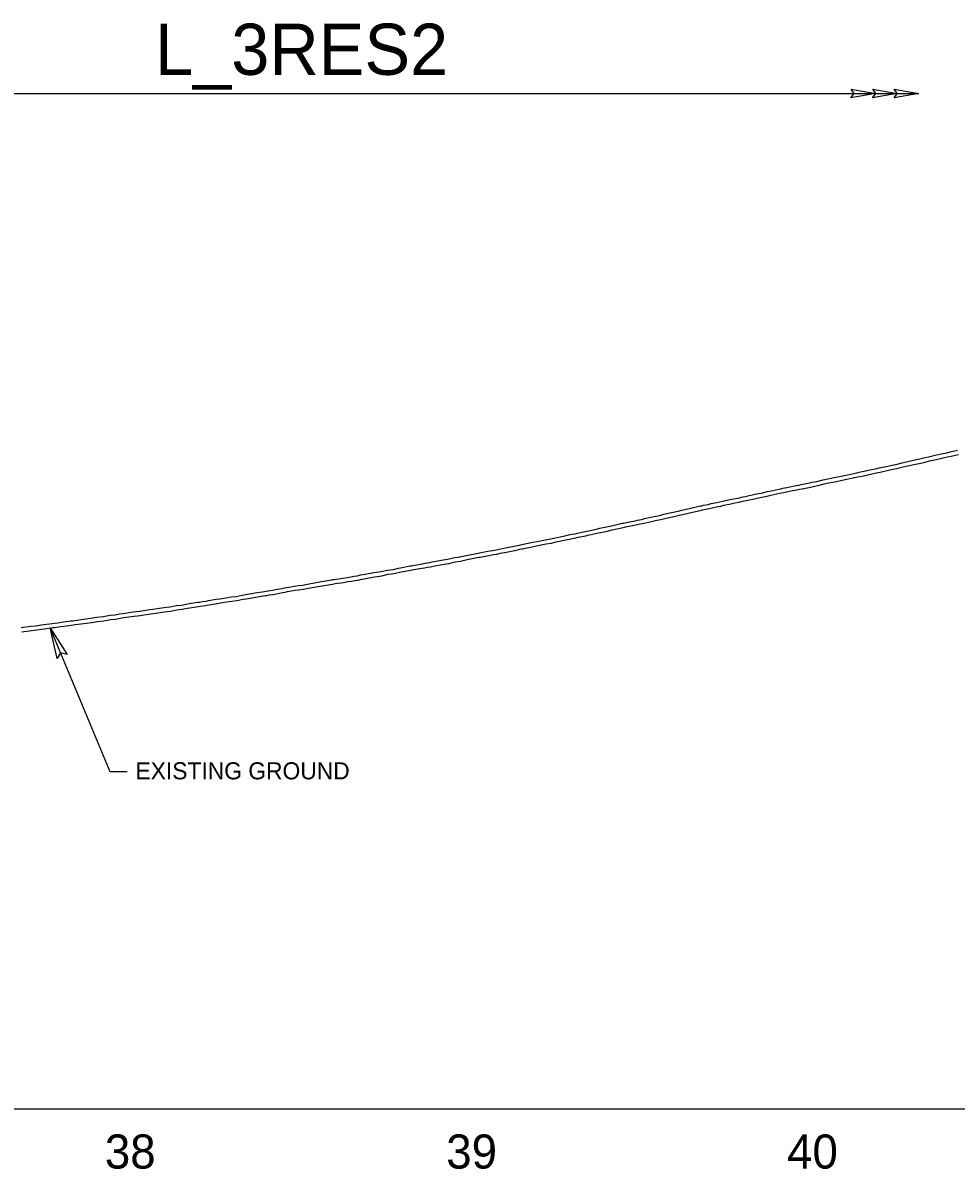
# Model space of a CAD drawing. Extents: x 2115752 to 2121174, y 562881 to 567245.
# Drawn here: x 2119464.8 to 2119738.2, y 566358.2 to 566694.2 of the extents above; entities that cross this region are included whole.
import ezdxf

# ---------------------------------------------------------------- set-up
doc = ezdxf.new("R2010")
doc.units = 0
for name, color, linetype in [('Exist Profile Cell', 7, 'Continuous'), ('Exist Vertical Profile Ground Line', 7, 'Continuous'), ('Exist Vertical Profile Horizontal Axis Label Major', 7, 'Continuous'), ('Prop Terminator CELL', 7, 'Continuous'), ('Prop VPI Label', 7, 'Continuous'), ('Scratch_Level_1', 7, 'Continuous')]:
    doc.layers.add(name, color=color, linetype=linetype)

msp = doc.modelspace()

# ---------------------------------------------------------------- linework, layer by layer
at = {"layer": 'Exist Profile Cell'}
msp.add_line((2116696.3, 566375.81), (2121174.42, 566375.81), dxfattribs=at)
at = {"layer": 'Exist Vertical Profile Ground Line'}
for points in [[(2119593.02, 566536.41), (2119594.92, 566536.88), (2119598.4, 566537.53), (2119598.78, 566537.61), (2119601.27, 566538.08), (2119602.62, 566538.34), (2119603.67, 566538.49), (2119604.59, 566538.7), (2119606.42, 566539.07), (2119607.87, 566539.37), (2119608.94, 566539.54), (2119610.39, 566539.9), (2119610.84, 566539.98), (2119611.18, 566540.05), (2119614.4, 566540.72), (2119615.66, 566540.98), (2119617.61, 566541.36), (2119617.98, 566541.44), (2119619.66, 566541.69), (2119621.01, 566542.03), (2119622.02, 566542.24), (2119624.23, 566542.72), (2119624.91, 566542.84), (2119625.83, 566543.06), (2119626.82, 566543.23), (2119627.5, 566543.39), (2119629.68, 566543.87), (2119630.29, 566543.98), (2119630.83, 566544.11), (2119633.41, 566544.67), (2119634.04, 566544.81), (2119635.59, 566545.09), (2119637.47, 566545.58), (2119640.62, 566546.26), (2119640.99, 566546.34), (2119641.38, 566546.43), (2119643.85, 566546.93), (2119644.4, 566547.04), (2119645.13, 566547.22), (2119646.25, 566547.43), (2119647.17, 566547.66), (2119648.99, 566548.06), (2119650.5, 566548.39), (2119651.67, 566548.61), (2119652.88, 566548.94), (2119653.75, 566549.14), (2119655.1, 566549.41), (2119657.04, 566549.88), (2119658.08, 566550.12), (2119660.62, 566550.7), (2119663.58, 566551.36), (2119663.93, 566551.44), (2119664.42, 566551.54), (2119665.82, 566551.79), (2119666.77, 566552.04), (2119668.34, 566552.39), (2119669.28, 566552.57), (2119670.15, 566552.78), (2119672.18, 566553.21), (2119673.36, 566553.46), (2119674.63, 566553.68), (2119676.14, 566554.05), (2119676.71, 566554.18), (2119679.49, 566554.79), (2119679.96, 566554.89), (2119681.81, 566555.24), (2119683.17, 566555.58), (2119683.87, 566555.74), (2119686.53, 566556.3), (2119687.07, 566556.41), (2119687.74, 566556.56), (2119688.89, 566556.78), (2119689.76, 566556.97), (2119691.57, 566557.33), (2119692.36, 566557.47), (2119693.1, 566557.63), (2119695.5, 566558.12), (2119696.31, 566558.29), (2119697.68, 566558.56), (2119699.56, 566559.03), (2119700.93, 566559.32), (2119703.17, 566559.8), (2119704.82, 566560.1), (2119706.17, 566560.42), (2119707.1, 566560.63), (2119709.38, 566561.11), (2119710.1, 566561.26), (2119710.98, 566561.46), (2119711.97, 566561.65), (2119712.73, 566561.81), (2119714.83, 566562.26), (2119715.95, 566562.53), (2119718.44, 566563.07), (2119718.85, 566563.15), (2119719.24, 566563.25), (2119720.79, 566563.54), (2119722.69, 566564.03), (2119726.33, 566564.86), (2119727.87, 566565.17), (2119729.01, 566565.46), (2119730.38, 566565.78)], [(2119730.38, 566565.78), (2119732.36, 566566.24), (2119734.06, 566566.61), (2119735.72, 566566.98), (2119736.75, 566567.2), (2119738.06, 566567.51), (2119738.89, 566567.69)], [(2119464.41, 566515.72), (2119467.25, 566516.09), (2119468.83, 566516.24), (2119470.32, 566516.48), (2119471.04, 566516.58), (2119473.53, 566516.91), (2119474.25, 566516.99), (2119475.12, 566517.12), (2119476.79, 566517.34), (2119478.92, 566517.64), (2119479.56, 566517.71), (2119480.11, 566517.81), (2119482.65, 566518.16), (2119483.34, 566518.26), (2119484.88, 566518.43), (2119486.64, 566518.73), (2119488.42, 566518.94), (2119489.98, 566519.21), (2119490.53, 566519.29), (2119491.92, 566519.44), (2119493.3, 566519.69), (2119494.31, 566519.84), (2119496.53, 566520.17), (2119497.26, 566520.27), (2119498.2, 566520.4), (2119499.07, 566520.48), (2119499.69, 566520.59), (2119502.12, 566520.94), (2119502.99, 566521.07), (2119506.29, 566521.57), (2119507.98, 566521.75), (2119509.89, 566522.13), (2119511.39, 566522.28), (2119512.86, 566522.58), (2119513.69, 566522.71), (2119516.1, 566523.1), (2119516.71, 566523.19), (2119517.56, 566523.34), (2119518.61, 566523.46), (2119519.37, 566523.61), (2119521.54, 566523.97), (2119522.65, 566524.14), (2119525.12, 566524.54), (2119525.96, 566524.66), (2119527.44, 566524.83), (2119529.29, 566525.23), (2119530.21, 566525.39), (2119532.53, 566525.77), (2119532.9, 566525.84), (2119535.76, 566526.3), (2119536.24, 566526.37), (2119536.88, 566526.5), (2119538.13, 566526.66), (2119539.05, 566526.86), (2119540.82, 566527.18), (2119541.61, 566527.3), (2119542.33, 566527.46), (2119544.54, 566527.85), (2119545.58, 566528.02), (2119546.88, 566528.14), (2119548.89, 566528.56), (2119552.46, 566529.19), (2119555.5, 566529.7), (2119555.83, 566529.75), (2119556.23, 566529.83), (2119558.74, 566530.19), (2119559.99, 566530.4), (2119561.05, 566530.56), (2119562.03, 566530.75), (2119562.97, 566530.87), (2119564.06, 566531.14), (2119564.71, 566531.25), (2119565.29, 566531.36), (2119567.77, 566531.81), (2119568.57, 566531.95), (2119569.94, 566532.12), (2119571.8, 566532.57), (2119573.54, 566532.77), (2119575.09, 566533.14), (2119575.61, 566533.23), (2119578.43, 566533.75), (2119578.85, 566533.82), (2119579.29, 566533.92), (2119581.62, 566534.33), (2119582.4, 566534.45), (2119583.35, 566534.65), (2119584.23, 566534.78), (2119584.93, 566534.94), (2119587.13, 566535.37), (2119587.67, 566535.45), (2119588.16, 566535.55), (2119589.56, 566535.75), (2119591.06, 566536.14), (2119591.51, 566536.23), (2119593.02, 566536.41)]]:
    msp.add_lwpolyline(points, dxfattribs=at)
at = {"layer": 'Prop Terminator CELL'}
msp.add_lwpolyline([(2119474.8, 566507.9), (2119472.77, 566516.81), (2119477.73, 566509.07), (2119475.81, 566509.51)], close=True, dxfattribs=at)
at = {"layer": 'Prop VPI Label'}
msp.add_lwpolyline([(2119495.3, 566474.67), (2119490.33, 566474.67), (2119472.77, 566516.81)], dxfattribs=at)
at = {"layer": 'Scratch_Level_1'}
msp.add_line((2119356.3, 566673.51), (2119727.28, 566673.51), dxfattribs=at)
for points in [[(2119707.44, 566674.75), (2119714.64, 566673.51), (2119707.4, 566672.23), (2119708.32, 566673.51)], [(2119713.76, 566674.75), (2119720.96, 566673.51), (2119713.72, 566672.23), (2119714.64, 566673.51)], [(2119720.08, 566674.75), (2119727.28, 566673.51), (2119720.04, 566672.23), (2119720.96, 566673.51)]]:
    msp.add_lwpolyline(points, close=True, dxfattribs=at)
for points in [[(2119730.1, 566567), (2119732.09, 566567.45), (2119733.79, 566567.83), (2119735.46, 566568.2), (2119736.47, 566568.42), (2119737.78, 566568.73), (2119738.62, 566568.91)], [(2119592.72, 566537.63), (2119594.65, 566538.1), (2119598.16, 566538.76), (2119598.54, 566538.84), (2119601.03, 566539.31), (2119602.41, 566539.57), (2119603.44, 566539.72), (2119604.32, 566539.93), (2119606.17, 566540.3), (2119607.65, 566540.6), (2119608.69, 566540.77), (2119610.13, 566541.12), (2119610.6, 566541.21), (2119610.92, 566541.27), (2119614.15, 566541.95), (2119615.42, 566542.21), (2119617.36, 566542.59), (2119617.76, 566542.67), (2119619.42, 566542.92), (2119620.73, 566543.25), (2119621.76, 566543.46), (2119623.99, 566543.94), (2119624.65, 566544.07), (2119625.58, 566544.28), (2119626.57, 566544.45), (2119627.22, 566544.61), (2119629.43, 566545.09), (2119630.03, 566545.21), (2119630.56, 566545.33), (2119633.14, 566545.89), (2119633.79, 566546.03), (2119635.32, 566546.32), (2119637.19, 566546.79), (2119640.36, 566547.49), (2119640.72, 566547.56), (2119641.11, 566547.65), (2119643.61, 566548.16), (2119644.13, 566548.26), (2119644.86, 566548.44), (2119645.98, 566548.66), (2119646.89, 566548.87), (2119648.72, 566549.28), (2119650.25, 566549.62), (2119651.39, 566549.83), (2119652.58, 566550.15), (2119653.49, 566550.37), (2119654.83, 566550.63), (2119656.75, 566551.1), (2119657.8, 566551.34), (2119660.35, 566551.92), (2119663.31, 566552.58), (2119663.66, 566552.66), (2119664.18, 566552.77), (2119665.55, 566553.01), (2119666.48, 566553.26), (2119668.09, 566553.62), (2119669.01, 566553.79), (2119669.87, 566554), (2119671.93, 566554.44), (2119673.12, 566554.68), (2119674.37, 566554.9), (2119675.85, 566555.27), (2119676.44, 566555.4), (2119679.22, 566556.01), (2119679.71, 566556.12), (2119681.54, 566556.46), (2119682.88, 566556.8), (2119683.6, 566556.96), (2119686.27, 566557.52), (2119686.8, 566557.63), (2119687.48, 566557.79), (2119688.64, 566558.01), (2119689.51, 566558.19), (2119691.33, 566558.56), (2119692.12, 566558.7), (2119692.84, 566558.86), (2119695.25, 566559.34), (2119696.06, 566559.52), (2119697.41, 566559.78), (2119699.28, 566560.24), (2119700.66, 566560.55), (2119702.93, 566561.03), (2119704.56, 566561.32), (2119705.9, 566561.64), (2119706.84, 566561.85), (2119709.13, 566562.34), (2119709.84, 566562.48), (2119710.73, 566562.68), (2119711.72, 566562.87), (2119712.46, 566563.03), (2119714.55, 566563.48), (2119715.67, 566563.75), (2119718.18, 566564.29), (2119718.58, 566564.38), (2119718.98, 566564.47), (2119720.52, 566564.76), (2119722.39, 566565.24), (2119726.07, 566566.08), (2119727.59, 566566.39), (2119728.71, 566566.68), (2119730.1, 566567)], [(2119464.25, 566516.96), (2119467.11, 566517.33), (2119468.67, 566517.48), (2119470.14, 566517.72), (2119470.88, 566517.82), (2119473.37, 566518.15), (2119474.08, 566518.23), (2119474.95, 566518.36), (2119476.62, 566518.58), (2119478.76, 566518.88), (2119479.39, 566518.95), (2119479.92, 566519.04), (2119482.48, 566519.4), (2119483.19, 566519.5), (2119484.7, 566519.67), (2119486.46, 566519.97), (2119488.25, 566520.17), (2119489.79, 566520.44), (2119490.37, 566520.53), (2119491.74, 566520.68), (2119493.1, 566520.93), (2119494.13, 566521.08), (2119496.35, 566521.41), (2119497.09, 566521.51), (2119498.06, 566521.65), (2119498.91, 566521.72), (2119499.48, 566521.83), (2119501.94, 566522.18), (2119502.8, 566522.3), (2119506.13, 566522.81), (2119507.79, 566522.98), (2119509.71, 566523.37), (2119511.21, 566523.52), (2119512.63, 566523.81), (2119513.49, 566523.95), (2119515.91, 566524.33), (2119516.51, 566524.42), (2119517.37, 566524.58), (2119518.41, 566524.7), (2119519.14, 566524.84), (2119521.34, 566525.21), (2119522.46, 566525.38), (2119524.93, 566525.77), (2119525.8, 566525.9), (2119527.24, 566526.06), (2119529.05, 566526.46), (2119530.01, 566526.63), (2119532.33, 566527.01), (2119532.7, 566527.07), (2119535.58, 566527.54), (2119536.03, 566527.6), (2119536.67, 566527.73), (2119537.92, 566527.9), (2119538.81, 566528.08), (2119540.62, 566528.41), (2119541.39, 566528.53), (2119542.09, 566528.68), (2119544.33, 566529.09), (2119545.43, 566529.26), (2119546.7, 566529.38), (2119548.65, 566529.79), (2119552.25, 566530.42), (2119555.3, 566530.93), (2119555.62, 566530.99), (2119556.02, 566531.06), (2119558.54, 566531.42), (2119559.78, 566531.64), (2119560.83, 566531.8), (2119561.83, 566531.99), (2119562.74, 566532.1), (2119563.81, 566532.36), (2119564.49, 566532.48), (2119565.06, 566532.59), (2119567.55, 566533.04), (2119568.39, 566533.19), (2119569.71, 566533.35), (2119571.58, 566533.8), (2119573.32, 566534), (2119574.83, 566534.36), (2119575.38, 566534.46), (2119578.21, 566534.99), (2119578.62, 566535.05), (2119579.05, 566535.14), (2119581.41, 566535.56), (2119582.17, 566535.68), (2119583.13, 566535.89), (2119584, 566536.01), (2119584.67, 566536.16), (2119586.91, 566536.6), (2119587.45, 566536.68), (2119587.95, 566536.78), (2119589.31, 566536.98), (2119590.79, 566537.36), (2119591.32, 566537.46), (2119592.87, 566537.65)]]:
    msp.add_lwpolyline(points, dxfattribs=at)

# ---------------------------------------------------------------- texts
at = {"layer": 'Exist Vertical Profile Horizontal Axis Label Major'}
for s, p in [('38', (2119488.77, 566358.31)), ('39', (2119588.81, 566358.31)), ('40', (2119688.69, 566358.31))]:
    msp.add_text(s, height=10, dxfattribs=at).set_placement(p)
at = {"layer": 'Prop VPI Label'}
msp.add_text('EXISTING GROUND', height=5, dxfattribs=at).set_placement((2119497.74, 566472.43))
at = {"layer": 'Scratch_Level_1'}
msp.add_text('L_3RES2', height=15, dxfattribs=at).set_placement((2119503.5, 566678.98))

doc.saveas('drawing.dxf')
